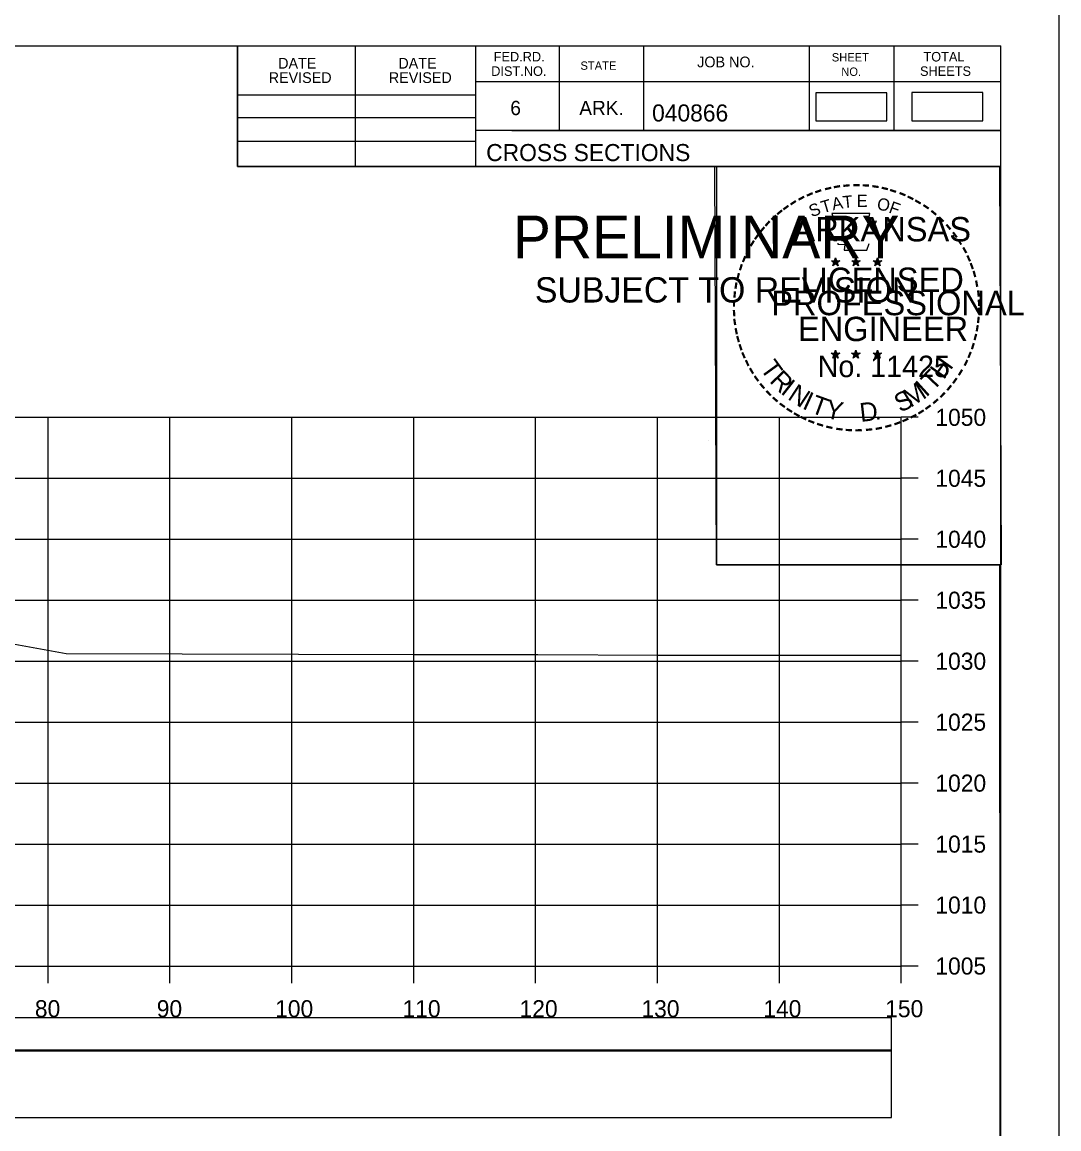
# Model space of a CAD drawing. Extents: x 1370565 to 1374448, y 301010 to 304637.
# Drawn here: x 1373446.7 to 1373531.7, y 302059 to 302149.7 of the extents above; entities that cross this region are included whole.
import ezdxf

# ---------------------------------------------------------------- set-up
doc = ezdxf.new("R2010")
doc.units = 0
for name, color, linetype in [('Default', 7, 'Continuous'), ('R_Axis', 7, 'Continuous'), ('R_Axis Annot', 7, 'Continuous'), ('R_Border', 7, 'Continuous'), ('R_Border PE', 7, 'Continuous'), ('R_Border Prem', 7, 'Continuous'), ('R_Drive', 7, 'Continuous'), ('R_Exist Surface', 7, 'Continuous'), ('R_Grid', 7, 'Continuous'), ('R_No Plot', 7, 'Continuous')]:
    doc.layers.add(name, color=color, linetype=linetype)

msp = doc.modelspace()

# ---------------------------------------------------------------- linework, layer by layer
at = {"layer": 'Default'}
for points in [[(1373511.808, 302141.615), (1373517.641, 302141.615), (1373517.641, 302143.926), (1373511.808, 302143.926)], [(1373219.605, 302065.352), (1373518.024, 302065.352), (1373518.024, 302068.058), (1373219.605, 302068.058)]]:
    msp.add_lwpolyline(points, close=True, dxfattribs=at)
at = {"layer": 'R_Axis'}
for p, q in [((1373518.814, 302072.313), (1373518.814, 302117.313)), ((1373520.214, 302117.313), (1373518.814, 302117.313)), ((1373520.214, 302112.313), (1373518.814, 302112.313)), ((1373520.214, 302107.313), (1373518.814, 302107.313)), ((1373520.214, 302102.313), (1373518.814, 302102.313)), ((1373520.214, 302097.313), (1373518.814, 302097.313)), ((1373520.214, 302092.313), (1373518.814, 302092.313)), ((1373520.214, 302087.313), (1373518.814, 302087.313)), ((1373520.214, 302082.313), (1373518.814, 302082.313)), ((1373520.214, 302077.313), (1373518.814, 302077.313)), ((1373218.814, 302072.313), (1373518.814, 302072.313)), ((1373448.814, 302070.913), (1373448.814, 302072.313)), ((1373458.814, 302070.913), (1373458.814, 302072.313)), ((1373468.814, 302070.913), (1373468.814, 302072.313)), ((1373478.814, 302070.913), (1373478.814, 302072.313)), ((1373488.814, 302070.913), (1373488.814, 302072.313)), ((1373498.814, 302070.913), (1373498.814, 302072.313)), ((1373508.814, 302070.913), (1373508.814, 302072.313)), ((1373518.814, 302070.913), (1373518.814, 302072.313)), ((1373520.214, 302072.313), (1373518.814, 302072.313))]:
    msp.add_line(p, q, dxfattribs=at)
at = {"layer": 'R_Border'}
for p, q in [((1373210.814, 302147.773), (1373526.994, 302147.773)), ((1373464.354, 302137.893), (1373464.354, 302147.773)), ((1373474.034, 302137.893), (1373474.034, 302147.773)), ((1373483.894, 302147.773), (1373483.894, 302137.893)), ((1373490.734, 302147.773), (1373490.734, 302140.833)), ((1373497.674, 302147.773), (1373497.674, 302140.833)), ((1373511.254, 302147.773), (1373511.254, 302140.833)), ((1373518.194, 302147.773), (1373518.194, 302140.833)), ((1373526.994, 301942.313), (1373526.994, 302147.773)), ((1373526.994, 302144.833), (1373483.894, 302144.833)), ((1373526.994, 302144.853), (1373526.994, 302144.853)), ((1373464.354, 302143.753), (1373483.894, 302143.753)), ((1373464.354, 302141.893), (1373483.894, 302141.893)), ((1373526.994, 302140.833), (1373483.894, 302140.833)), ((1373486.854, 302140.833), (1373526.994, 302140.833)), ((1373464.354, 302139.953), (1373483.894, 302139.953)), ((1373526.994, 302137.893), (1373464.354, 302137.893))]:
    msp.add_line(p, q, dxfattribs=at)
at = {"layer": 'R_Border PE'}
for p, q in [((1373513.079, 302130.148), (1373513.428, 302130.037)), ((1373513.079, 302130.148), (1373513.332, 302130.103)), ((1373513.079, 302130.148), (1373513.316, 302130.026)), ((1373513.212, 302129.74), (1373513.428, 302130.037)), ((1373513.212, 302129.74), (1373513.338, 302129.984)), ((1373513.212, 302129.74), (1373513.426, 302129.957)), ((1373513.428, 302130.402), (1373513.387, 302130.15)), ((1373513.641, 302129.74), (1373513.426, 302129.954)), ((1373513.428, 302130.037), (1373513.428, 302130.402)), ((1373513.428, 302130.402), (1373513.477, 302130.152)), ((1373513.775, 302130.148), (1373513.428, 302130.037)), ((1373513.641, 302129.74), (1373513.428, 302130.037)), ((1373513.775, 302130.148), (1373513.489, 302130.099)), ((1373513.641, 302129.74), (1373513.504, 302130.031)), ((1373513.775, 302130.148), (1373513.571, 302130.046)), ((1373514.749, 302130.148), (1373515.098, 302130.037)), ((1373514.749, 302130.148), (1373515.002, 302130.103)), ((1373514.749, 302130.148), (1373514.986, 302130.026)), ((1373514.882, 302129.74), (1373515.098, 302130.037)), ((1373514.882, 302129.74), (1373515.008, 302129.984)), ((1373514.882, 302129.74), (1373515.096, 302129.957)), ((1373515.098, 302130.402), (1373515.057, 302130.15)), ((1373515.311, 302129.74), (1373515.096, 302129.954)), ((1373515.098, 302130.037), (1373515.098, 302130.402)), ((1373515.098, 302130.402), (1373515.147, 302130.152)), ((1373515.445, 302130.148), (1373515.098, 302130.037)), ((1373515.311, 302129.74), (1373515.098, 302130.037)), ((1373515.445, 302130.148), (1373515.159, 302130.099)), ((1373515.311, 302129.74), (1373515.174, 302130.031)), ((1373515.445, 302130.148), (1373515.241, 302130.046)), ((1373516.513, 302130.136), (1373516.862, 302130.025)), ((1373516.513, 302130.136), (1373516.766, 302130.091)), ((1373516.513, 302130.136), (1373516.75, 302130.014)), ((1373516.646, 302129.728), (1373516.862, 302130.025)), ((1373516.646, 302129.728), (1373516.772, 302129.972)), ((1373516.646, 302129.728), (1373516.86, 302129.945)), ((1373516.862, 302130.39), (1373516.821, 302130.138)), ((1373517.075, 302129.728), (1373516.86, 302129.942)), ((1373516.862, 302130.025), (1373516.862, 302130.39)), ((1373516.862, 302130.39), (1373516.911, 302130.14)), ((1373517.209, 302130.136), (1373516.862, 302130.025)), ((1373517.075, 302129.728), (1373516.862, 302130.025)), ((1373517.209, 302130.136), (1373516.923, 302130.087)), ((1373517.075, 302129.728), (1373516.938, 302130.019)), ((1373517.209, 302130.136), (1373517.005, 302130.034)), ((1373513.075, 302122.575), (1373513.424, 302122.464)), ((1373513.075, 302122.575), (1373513.328, 302122.53)), ((1373513.075, 302122.575), (1373513.312, 302122.453)), ((1373513.208, 302122.167), (1373513.424, 302122.464)), ((1373513.208, 302122.167), (1373513.334, 302122.411)), ((1373513.208, 302122.167), (1373513.422, 302122.384)), ((1373513.424, 302122.829), (1373513.383, 302122.577)), ((1373513.637, 302122.167), (1373513.422, 302122.381)), ((1373513.424, 302122.464), (1373513.424, 302122.829)), ((1373513.424, 302122.829), (1373513.473, 302122.579)), ((1373513.771, 302122.575), (1373513.424, 302122.464)), ((1373513.637, 302122.167), (1373513.424, 302122.464)), ((1373513.771, 302122.575), (1373513.485, 302122.526)), ((1373513.637, 302122.167), (1373513.5, 302122.458)), ((1373513.771, 302122.575), (1373513.567, 302122.473)), ((1373514.744, 302122.575), (1373515.093, 302122.464)), ((1373514.744, 302122.575), (1373514.997, 302122.53)), ((1373514.744, 302122.575), (1373514.981, 302122.453)), ((1373514.877, 302122.167), (1373515.093, 302122.464)), ((1373514.877, 302122.167), (1373515.003, 302122.411)), ((1373514.877, 302122.167), (1373515.091, 302122.384)), ((1373515.093, 302122.829), (1373515.052, 302122.577)), ((1373515.306, 302122.167), (1373515.091, 302122.381)), ((1373515.093, 302122.464), (1373515.093, 302122.829)), ((1373515.093, 302122.829), (1373515.142, 302122.579)), ((1373515.44, 302122.575), (1373515.093, 302122.464)), ((1373515.306, 302122.167), (1373515.093, 302122.464)), ((1373515.44, 302122.575), (1373515.154, 302122.526)), ((1373515.306, 302122.167), (1373515.169, 302122.458)), ((1373515.44, 302122.575), (1373515.236, 302122.473)), ((1373516.511, 302122.565), (1373516.86, 302122.454)), ((1373516.511, 302122.565), (1373516.764, 302122.52)), ((1373516.511, 302122.565), (1373516.748, 302122.443)), ((1373516.644, 302122.157), (1373516.86, 302122.454)), ((1373516.644, 302122.157), (1373516.77, 302122.401)), ((1373516.644, 302122.157), (1373516.858, 302122.374)), ((1373516.86, 302122.819), (1373516.819, 302122.567)), ((1373517.073, 302122.157), (1373516.858, 302122.371)), ((1373516.86, 302122.454), (1373516.86, 302122.819)), ((1373516.86, 302122.819), (1373516.909, 302122.569)), ((1373517.207, 302122.565), (1373516.86, 302122.454)), ((1373517.073, 302122.157), (1373516.86, 302122.454)), ((1373517.207, 302122.565), (1373516.921, 302122.516)), ((1373517.073, 302122.157), (1373516.936, 302122.448)), ((1373517.207, 302122.565), (1373517.003, 302122.463))]:
    msp.add_line(p, q, dxfattribs=at)
for points in [[(1373513.12, 302134.026), (1373513.389, 302133.199)], [(1373516.631, 302133.104), (1373516.773, 302133.388), (1373516.088, 302133.364), (1373516.236, 302134.026), (1373513.12, 302134.026)], [(1373513.612, 302131.603), (1373513.612, 302131.516), (1373514.175, 302131.497), (1373514.121, 302131.024), (1373515.991, 302131.024), (1373516.192, 302131.56)], [(1373513.428, 302130.402), (1373513.641, 302129.74), (1373513.079, 302130.148), (1373513.775, 302130.148), (1373513.212, 302129.74), (1373513.428, 302130.402)], [(1373515.098, 302130.402), (1373515.311, 302129.74), (1373514.749, 302130.148), (1373515.445, 302130.148), (1373514.882, 302129.74), (1373515.098, 302130.402)], [(1373516.862, 302130.39), (1373517.075, 302129.728), (1373516.513, 302130.136), (1373517.209, 302130.136), (1373516.646, 302129.728), (1373516.862, 302130.39)], [(1373513.424, 302122.829), (1373513.637, 302122.167), (1373513.075, 302122.575), (1373513.771, 302122.575), (1373513.208, 302122.167), (1373513.424, 302122.829)], [(1373515.093, 302122.829), (1373515.306, 302122.167), (1373514.744, 302122.575), (1373515.44, 302122.575), (1373514.877, 302122.167), (1373515.093, 302122.829)], [(1373516.86, 302122.819), (1373517.073, 302122.157), (1373516.511, 302122.565), (1373517.207, 302122.565), (1373516.644, 302122.157), (1373516.86, 302122.819)]]:
    msp.add_lwpolyline(points, dxfattribs=at)
for centre, radius in [((1373513.427, 302130.036), 0.172), ((1373513.427, 302130.036), 0.145), ((1373513.427, 302130.036), 0.116), ((1373513.427, 302130.036), 0.0991), ((1373513.427, 302130.036), 0.0747), ((1373513.427, 302130.036), 0.0495), ((1373513.427, 302130.036), 0.0296), ((1373515.097, 302130.036), 0.172), ((1373515.097, 302130.036), 0.145), ((1373515.097, 302130.036), 0.116), ((1373515.097, 302130.036), 0.0991), ((1373515.097, 302130.036), 0.0747), ((1373515.097, 302130.036), 0.0495), ((1373515.097, 302130.036), 0.0296), ((1373516.861, 302130.024), 0.172), ((1373516.861, 302130.024), 0.145), ((1373516.861, 302130.024), 0.116), ((1373516.861, 302130.024), 0.0991), ((1373516.861, 302130.024), 0.0747), ((1373516.861, 302130.024), 0.0495), ((1373516.861, 302130.024), 0.0296), ((1373513.423, 302122.463), 0.172), ((1373513.423, 302122.463), 0.145), ((1373513.423, 302122.463), 0.116), ((1373513.423, 302122.463), 0.0991), ((1373513.423, 302122.463), 0.0747), ((1373513.423, 302122.463), 0.0495), ((1373513.423, 302122.463), 0.0296), ((1373515.092, 302122.463), 0.172), ((1373515.092, 302122.463), 0.145), ((1373515.092, 302122.463), 0.116), ((1373515.092, 302122.463), 0.0991), ((1373515.092, 302122.463), 0.0747), ((1373515.092, 302122.463), 0.0495), ((1373515.092, 302122.463), 0.0296), ((1373516.859, 302122.453), 0.172), ((1373516.859, 302122.453), 0.145), ((1373516.859, 302122.453), 0.116), ((1373516.859, 302122.453), 0.0991), ((1373516.859, 302122.453), 0.0747), ((1373516.859, 302122.453), 0.0495), ((1373516.859, 302122.453), 0.0296)]:
    msp.add_circle(centre, radius, dxfattribs=at)
at = {"layer": 'R_Drive'}
for points in [[(1373519.678, 302141.625), (1373525.511, 302141.625), (1373525.511, 302143.936), (1373519.678, 302143.936)], [(1373219.605, 302059.885), (1373518.024, 302059.885), (1373518.024, 302065.407), (1373219.605, 302065.407)]]:
    msp.add_lwpolyline(points, close=True, dxfattribs=at)
at = {"layer": 'R_Exist Surface'}
msp.add_lwpolyline([(1373218.814, 302086.327), (1373226.138, 302086.171), (1373229.561, 302086.436), (1373237.69, 302087.185), (1373237.851, 302087.233), (1373238.304, 302087.402), (1373257.325, 302094.172), (1373259.505, 302094.948), (1373319.066, 302094.647), (1373332.97, 302097.2), (1373353.078, 302097.162), (1373372.665, 302097.216), (1373385.558, 302099.405), (1373402.836, 302102.553), (1373408.439, 302102.796), (1373413.135, 302102.974), (1373419.151, 302102.936), (1373423.277, 302102.898), (1373434.928, 302100.743), (1373450.303, 302097.93), (1373478.874, 302097.849), (1373488.984, 302097.849), (1373498.868, 302097.812), (1373518.814, 302097.803)], dxfattribs=at)
at = {"layer": 'R_Grid'}
for p, q in [((1373218.814, 302117.312), (1373518.814, 302117.312)), ((1373448.814, 302072.312), (1373448.814, 302117.312)), ((1373458.814, 302072.312), (1373458.814, 302117.312)), ((1373468.814, 302072.312), (1373468.814, 302117.312)), ((1373478.814, 302072.312), (1373478.814, 302117.312)), ((1373488.814, 302072.312), (1373488.814, 302117.312)), ((1373498.814, 302072.312), (1373498.814, 302117.312)), ((1373508.814, 302072.312), (1373508.814, 302117.312)), ((1373518.814, 302072.312), (1373518.814, 302117.312)), ((1373218.814, 302112.312), (1373518.814, 302112.312)), ((1373218.814, 302107.312), (1373518.814, 302107.312)), ((1373218.814, 302102.312), (1373518.814, 302102.312)), ((1373218.814, 302097.312), (1373518.814, 302097.312)), ((1373218.814, 302092.312), (1373518.814, 302092.312)), ((1373218.814, 302087.312), (1373518.814, 302087.312)), ((1373218.814, 302082.312), (1373518.814, 302082.312)), ((1373218.814, 302077.312), (1373518.814, 302077.312)), ((1373218.814, 302072.312), (1373518.814, 302072.312))]:
    msp.add_line(p, q, dxfattribs=at)
at = {"layer": 'R_No Plot'}
msp.add_line((1373503.029, 302115.437), (1373503.029, 302115.437), dxfattribs=at)
for points in [[(1373198.407, 302151.667), (1373531.747, 302151.667), (1373531.747, 301938.33), (1373198.407, 301938.33)], [(1373444.734, 302147.773), (1373464.354, 302147.773), (1373464.354, 302137.893), (1373480.467, 302137.893), (1373503.666, 302137.893), (1373503.666, 302105.222), (1373526.874, 302105.222), (1373526.994, 301942.313), (1373210.814, 301942.313), (1373210.814, 302147.773)], [(1373503.526, 302137.893), (1373526.874, 302137.893), (1373527.014, 302105.222), (1373503.666, 302105.222)]]:
    msp.add_lwpolyline(points, close=True, dxfattribs=at)

# ---------------------------------------------------------------- texts
at = {"layer": 'R_Axis Annot'}
for s, p in [('1050', (1373521.614, 302116.613)), ('1045', (1373521.614, 302111.613)), ('1040', (1373521.614, 302106.613)), ('1035', (1373521.614, 302101.613)), ('1030', (1373521.614, 302096.613)), ('1025', (1373521.614, 302091.613)), ('1020', (1373521.614, 302086.613)), ('1015', (1373521.614, 302081.613)), ('1010', (1373521.614, 302076.613)), ('1005', (1373521.614, 302071.613)), ('80', (1373447.729, 302068.113)), ('90', (1373457.729, 302068.113)), ('100', (1373467.442, 302068.113)), ('110', (1373477.894, 302068.113)), ('120', (1373487.497, 302068.113)), ('130', (1373497.497, 302068.113)), ('140', (1373507.497, 302068.113)), ('150', (1373517.497, 302068.113))]:
    msp.add_text(s, height=1.4, dxfattribs=at).set_placement(p)
at = {"layer": 'R_Border'}
for s, height, p in [('FED.RD.', 0.7819, (1373485.374, 302146.493)), ('JOB NO.', 0.8792, (1373502.074, 302146.013)), ('SHEET', 0.684, (1373513.114, 302146.493)), ('TOTAL', 0.7819, (1373520.634, 302146.493)), ('DATE', 0.8792, (1373467.692, 302145.909)), ('DATE', 0.8792, (1373477.552, 302145.909)), ('DIST.NO.', 0.7819, (1373485.174, 302145.313)), ('STATE', 0.684, (1373492.494, 302145.813)), ('NO.', 0.684, (1373513.894, 302145.313)), ('SHEETS', 0.7819, (1373520.354, 302145.313)), ('REVISED', 0.8792, (1373466.912, 302144.729)), ('REVISED', 0.8792, (1373476.772, 302144.729)), ('6', 1.172, (1373486.734, 302142.093)), ('ARK.', 1.1723, (1373492.394, 302142.093)), ('040866', 1.4, (1373498.37, 302141.572)), ('CROSS SECTIONS', 1.4, (1373484.758, 302138.323))]:
    msp.add_text(s, height=height, rotation=360, dxfattribs=at).set_placement(p)
at = {"layer": 'R_Border PE'}
for s, height, rotation, p in [('-', 1.6, 19.17608, (1373511.868, 302135.153)), ('-', 1.6, 13.63015, (1373512.618, 302135.394)), ('-', 1.6, 10.21935, (1373513.296, 302135.556)), ('-', 1.6, 5.89682, (1373514.025, 302135.666)), ('-', 1.6, 0.18623, (1373514.797, 302135.738)), ('-', 1.6, 357.74304, (1373515.52, 302135.725)), ('-', 1.6, 352.16172, (1373516.264, 302135.669)), ('-', 1.6, 347.20489, (1373516.983, 302135.555)), ('-', 1.6, 342.3362, (1373517.618, 302135.4)), ('-', 1.6, 34.06357, (1373510.004, 302134.197)), ('-', 1.6, 28.79182, (1373510.601, 302134.567)), ('-', 1.6, 24.30721, (1373511.234, 302134.884)), ('T', 1, 16.4036, (1373512.389, 302134.035)), ('A', 1, 11.21318, (1373513.215, 302134.286)), ('T', 1, 6.02276, (1373514.064, 302134.452)), ('E', 1, 0.83234, (1373515.169, 302134.562)), ('O', 1, 350.4515, (1373516.773, 302134.352)), ('-', 1.6, 337.85509, (1373518.353, 302135.177)), ('-', 1.6, 334.12109, (1373518.984, 302134.906)), ('-', 1.6, 329.64089, (1373519.563, 302134.623)), ('-', 1.6, 38.95066, (1373508.95, 302133.424)), ('-', 1.6, 36.23174, (1373509.426, 302133.802)), ('S', 1, 21.59401, (1373511.475, 302133.704)), ('F', 1, 340.07066, (1373517.727, 302134.124)), ('-', 1.6, 325.86266, (1373520.206, 302134.262)), ('-', 1.6, 320.52971, (1373520.816, 302133.836)), ('-', 1.6, 48.42305, (1373508.069, 302132.529)), ('-', 1.6, 42.96224, (1373508.517, 302133.007)), ('ARKANSAS', 2, 360, (1373509.973, 302131.738)), ('-', 1.6, 315.57859, (1373521.415, 302133.348)), ('-', 1.6, 54.23247, (1373507.253, 302131.476)), ('-', 1.6, 50.61417, (1373507.666, 302132.043)), ('-', 1.6, 309.87973, (1373521.984, 302132.798)), ('-', 1.6, 306.65218, (1373522.509, 302132.196)), ('-', 1.6, 58.07063, (1373506.928, 302130.949)), ('-', 1.4, 303.67529, (1373522.995, 302131.628)), ('-', 1.6, 67.77427, (1373506.356, 302129.724)), ('-', 1.6, 62.87135, (1373506.615, 302130.335)), ('-', 1.6, 299.66835, (1373523.314, 302131.021)), ('-', 1.6, 294.66279, (1373523.638, 302130.409)), ('-', 1.6, 72.39447, (1373506.137, 302129.094)), ('LICENSED', 2, 360, (1373510.571, 302127.589)), ('DWB', 0.01, 360, (1373513.415, 302130.031)), ('DWB', 0.01, 360, (1373515.085, 302130.031)), ('DWB', 0.01, 360, (1373516.849, 302130.021)), ('-', 1.6, 290.57283, (1373523.895, 302129.832)), ('-', 1.6, 75.46096, (1373505.94, 302128.38)), ('-', 1.6, 285.12326, (1373524.129, 302129.252)), ('-', 1.6, 81.20126, (1373505.808, 302127.667)), ('-', 1.6, 280.54934, (1373524.329, 302128.51)), ('-', 1.6, 89.06224, (1373505.707, 302126.275)), ('-', 1.6, 85.18634, (1373505.732, 302126.976)), ('PROFESSIONAL', 2, 360, (1373508.147, 302125.685)), ('-', 1.6, 276.59616, (1373524.491, 302127.742)), ('-', 1.6, 274.33011, (1373524.551, 302127.02)), ('-', 1.6, 94.19588, (1373505.742, 302125.55)), ('-', 1.6, 269.94067, (1373524.585, 302126.388)), ('-', 1.6, 98.94793, (1373505.814, 302124.883)), ('ENGINEER', 2, 360, (1373510.334, 302123.56)), ('-', 1.6, 263.5172, (1373524.566, 302125.722)), ('-', 1.6, 101.71495, (1373505.949, 302124.15)), ('-', 1.6, 255.7626, (1373524.385, 302124.39)), ('-', 1.6, 260.99529, (1373524.495, 302125.068)), ('-', 1.6, 105.45785, (1373506.111, 302123.555)), ('-', 1.6, 109.08742, (1373506.326, 302122.924)), ('-', 1.6, 252.86809, (1373524.204, 302123.67)), ('-', 1.6, 114.06432, (1373506.58, 302122.328)), ('No. 11425', 1.757, 360, (1373511.962, 302120.609)), ('DWB', 0.01, 360, (1373513.411, 302122.459)), ('DWB', 0.01, 360, (1373515.08, 302122.459)), ('DWB', 0.01, 360, (1373516.847, 302122.449)), ('-', 1.6, 247.88866, (1373523.981, 302122.997)), ('-', 1.6, 115.72885, (1373506.885, 302121.71)), ('T', 1.54, 306.04056, (1373507.184, 302121.302)), ('H', 1.54, 54.60883, (1373522.304, 302120.337)), ('-', 1.6, 244.61971, (1373523.719, 302122.368)), ('-', 1.6, 120.44712, (1373507.242, 302121.124)), ('-', 1.6, 125.89344, (1373507.645, 302120.563)), ('R', 1.54, 314.00497, (1373507.946, 302120.254)), ('T', 1.54, 46.64442, (1373521.415, 302119.395)), ('-', 1.6, 233.84524, (1373522.923, 302120.963)), ('-', 1.6, 239.07125, (1373523.325, 302121.616)), ('-', 1.6, 130.71812, (1373508.107, 302120.011)), ('I', 1.54, 321.96938, (1373508.847, 302119.322)), ('N', 1.54, 326.50021, (1373509.414, 302118.851)), ('M', 1.54, 32.65632, (1373519.569, 302118.07)), ('I', 1.54, 42.11359, (1373520.853, 302118.917)), ('-', 1.6, 231.25377, (1373522.493, 302120.397)), ('-', 1.6, 134.22381, (1373508.624, 302119.466)), ('-', 1.6, 138.93382, (1373509.149, 302119.002)), ('I', 1.54, 335.36034, (1373510.622, 302118.065)), ('T', 1.54, 339.89117, (1373511.283, 302117.737)), ('Y', 1.54, 347.85558, (1373512.5, 302117.292)), ('S', 1.54, 26.9312, (1373518.73, 302117.664)), ('-', 1.6, 221.08509, (1373521.492, 302119.324)), ('-', 1.6, 225.76533, (1373522.014, 302119.833)), ('-', 1.6, 144.64634, (1373509.705, 302118.596)), ('-', 1.6, 148.08978, (1373510.266, 302118.225)), ('D', 1.54, 6.39691, (1373515.485, 302116.933)), ('-', 1.6, 212.24909, (1373520.409, 302118.465)), ('-', 1.6, 215.73633, (1373520.943, 302118.852)), ('-', 1.6, 151.57039, (1373510.845, 302117.9)), ('-', 1.6, 154.60019, (1373511.367, 302117.653)), ('-', 1.6, 158.56121, (1373511.991, 302117.399)), ('.', 1.54, 13.76417, (1373516.677, 302117.061)), ('-', 1.6, 200.71842, (1373518.608, 302117.527)), ('-', 1.6, 204.25161, (1373519.227, 302117.8)), ('-', 1.6, 207.35684, (1373519.851, 302118.119)), ('-', 1.6, 162.79826, (1373512.678, 302117.186)), ('-', 1.6, 167.55551, (1373513.393, 302117.022)), ('-', 1.6, 173.11546, (1373514.165, 302116.912)), ('-', 1.6, 176.51827, (1373514.913, 302116.859)), ('-', 1.6, 181.59176, (1373515.657, 302116.878)), ('-', 1.6, 185.81666, (1373516.466, 302116.954)), ('-', 1.6, 191.28576, (1373517.202, 302117.086)), ('-', 1.6, 195.47429, (1373517.931, 302117.285))]:
    msp.add_text(s, height=height, rotation=rotation, dxfattribs=at).set_placement(p)
at = {"layer": 'R_Border Prem'}
for s, height, p in [('PRELIMINARY', 3.5, (1373486.946, 302130.356)), ('DWB', 0.01, (1373487.692, 302132.205)), ('SUBJECT TO REVISION', 2.07511, (1373488.755, 302126.727))]:
    msp.add_text(s, height=height, rotation=360, dxfattribs=at).set_placement(p)

doc.saveas('drawing.dxf')
